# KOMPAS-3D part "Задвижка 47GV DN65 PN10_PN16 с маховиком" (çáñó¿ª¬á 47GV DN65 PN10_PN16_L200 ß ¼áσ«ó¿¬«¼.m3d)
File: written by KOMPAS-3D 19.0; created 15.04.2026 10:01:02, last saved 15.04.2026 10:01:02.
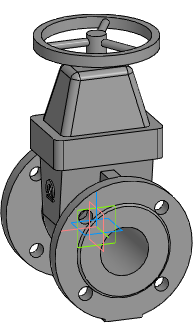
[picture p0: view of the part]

Document properties: Автор: Евгений; Полное имя файла: Z:\3.Личные\kachalov\3d для проектировщиков\2.1 Тип 47GV, 47GV.Z\Задвижка 47GV_DN40-DN600\stp_Задвижка 47GV\Задвижка 47GV DN65 PN10_PN16_L200 с маховиком.m3d

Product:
- Part/product: Задвижка 47GV DN65 PN10_PN16 с маховиком

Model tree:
1. Операция без истории:1  (labels: Задвижка 47GV DN65 PN10_PN16 с маховиком)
